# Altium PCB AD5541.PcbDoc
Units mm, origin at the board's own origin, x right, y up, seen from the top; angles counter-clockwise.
Board outline 64.13 x 29.21 mm, 2 copper layers (Top Layer, Bottom Layer); 40 components, 20 nets, 121 pads, 208 vias.
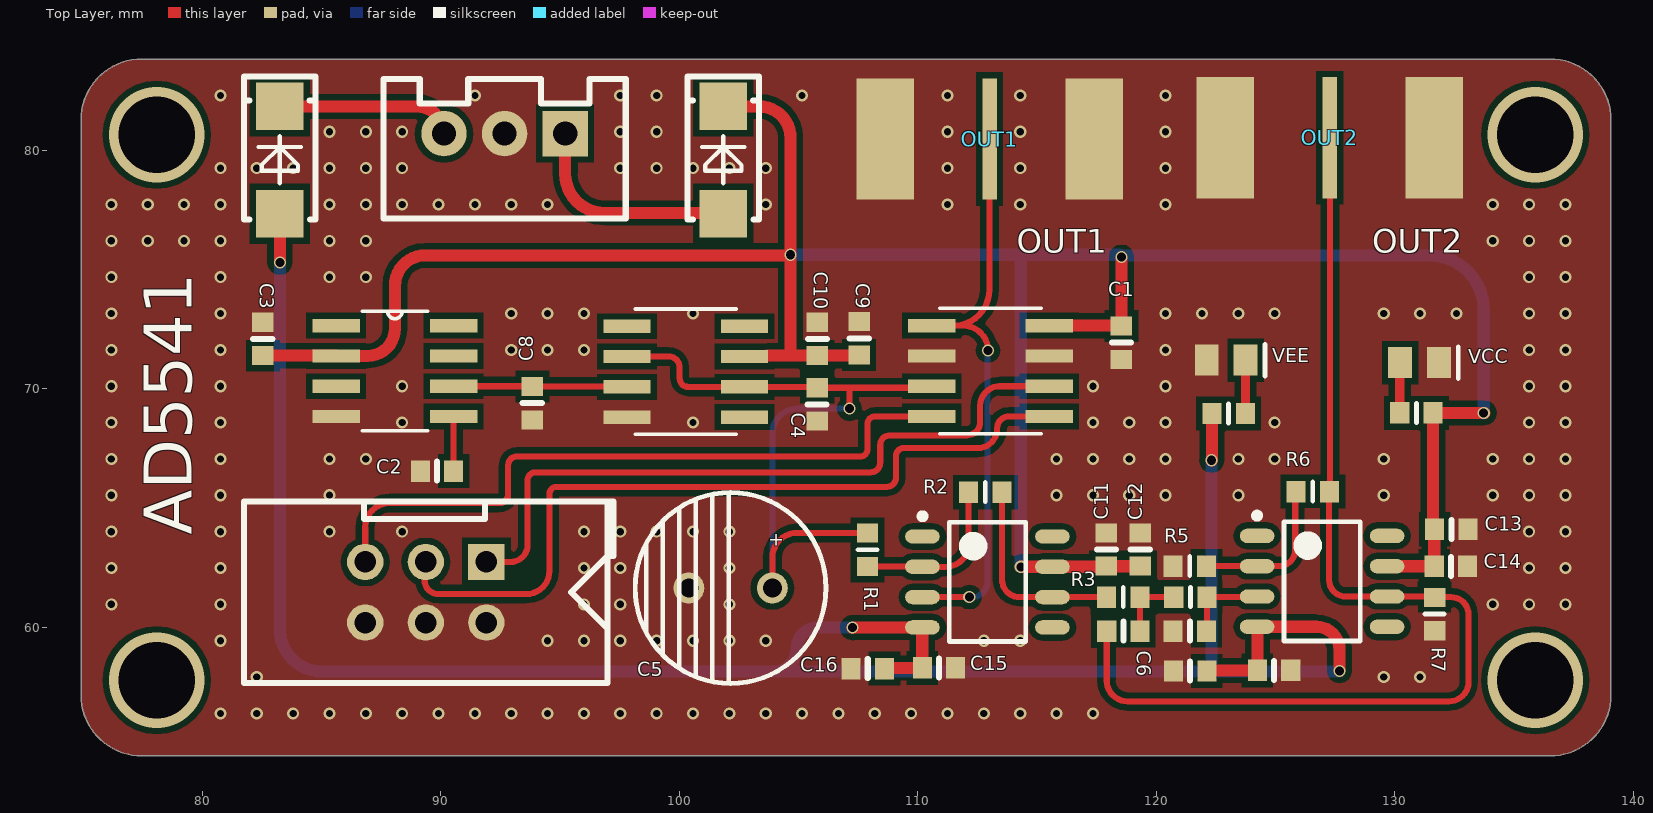
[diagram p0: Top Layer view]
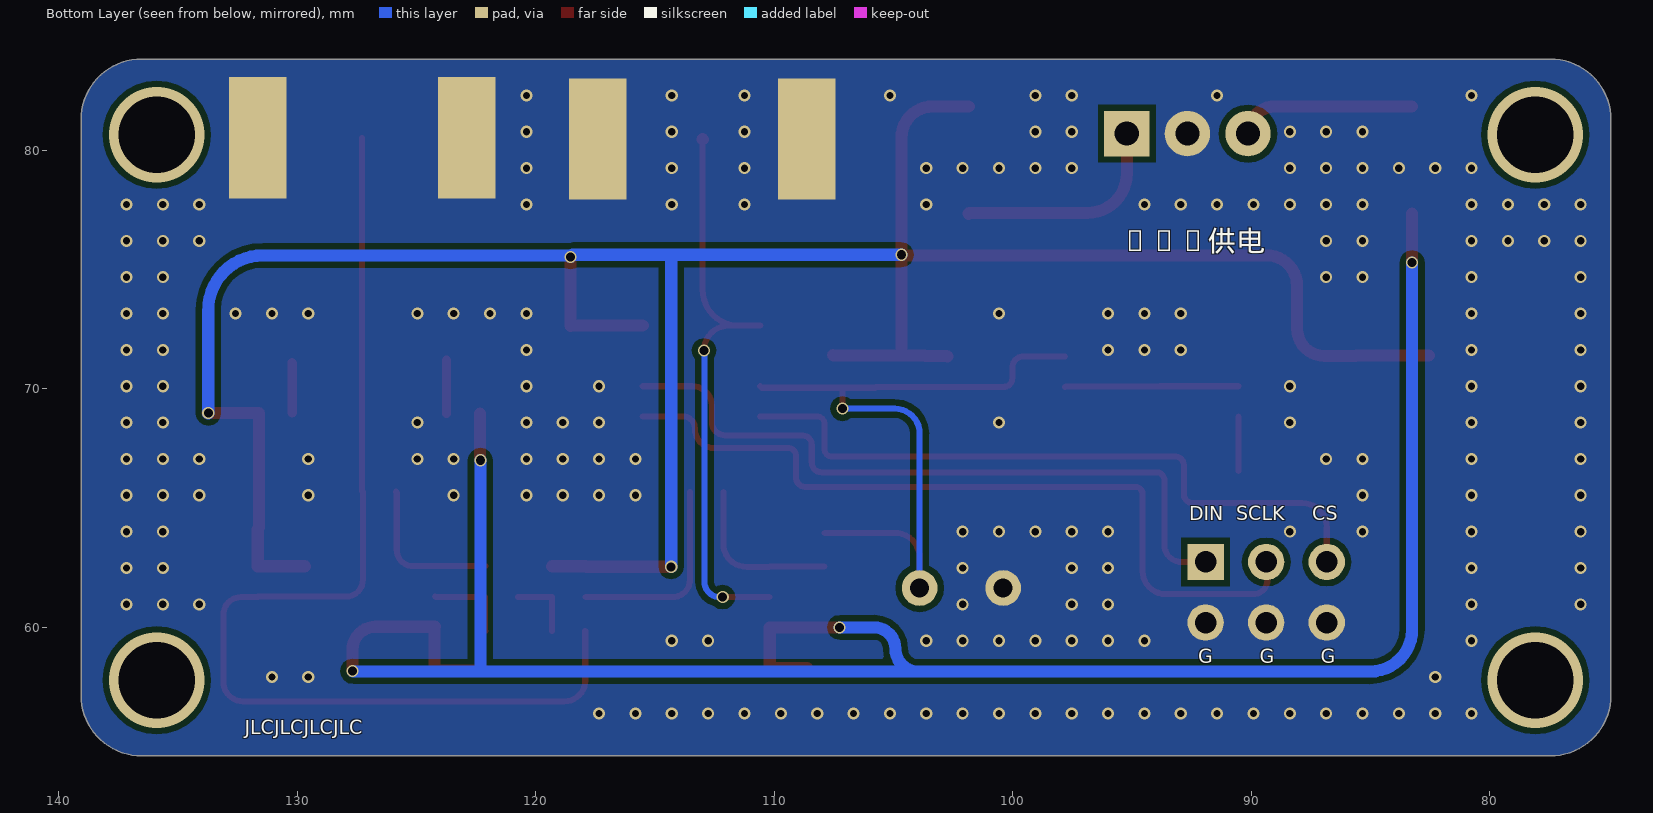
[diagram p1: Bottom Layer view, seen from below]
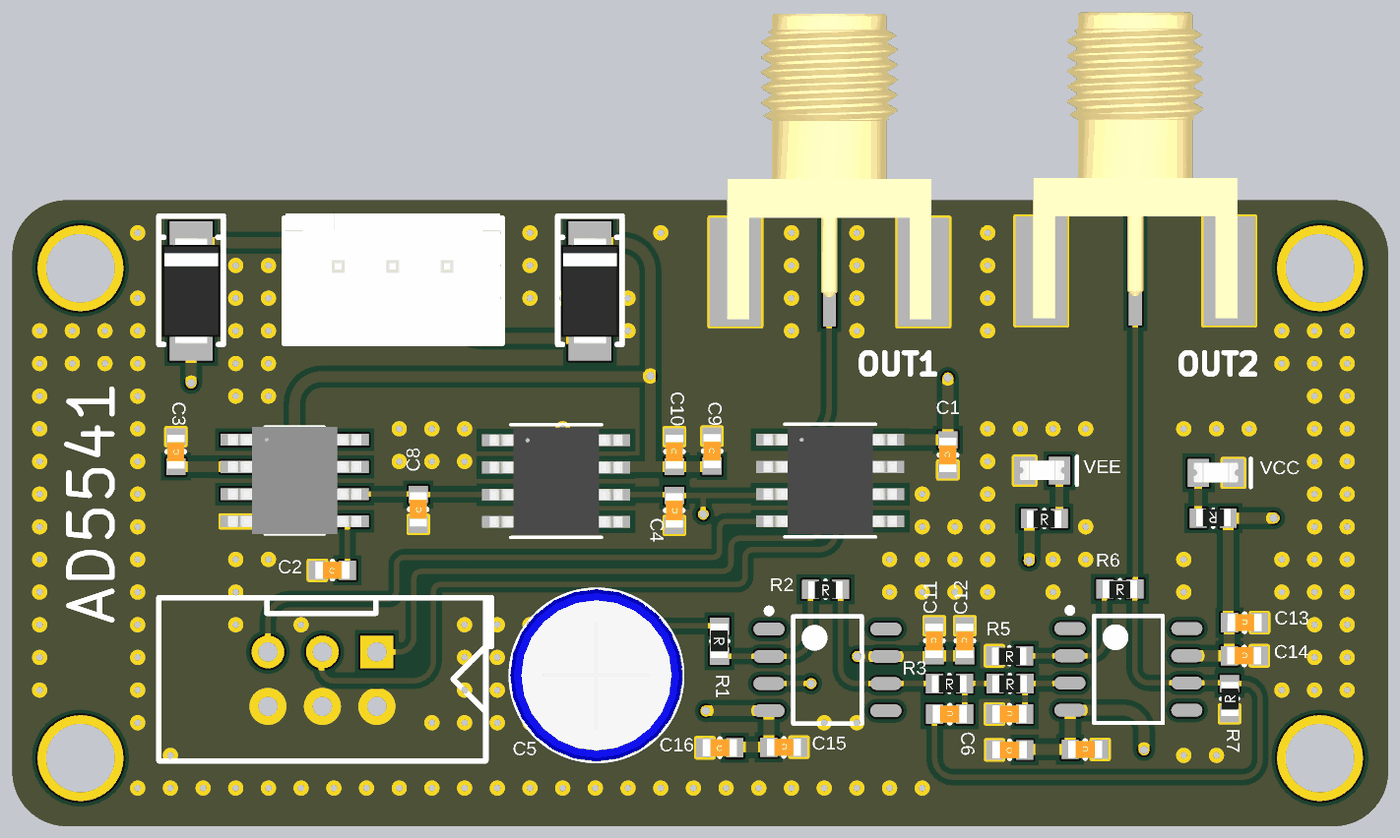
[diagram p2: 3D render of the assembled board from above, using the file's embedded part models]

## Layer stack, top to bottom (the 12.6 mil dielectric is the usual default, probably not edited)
Top Solder: solder mask 0.0102, Solder Resist, Dk 3.5
Top Layer: signal copper 0.0356
Dielectric 1: dielectric 0.32, FR-4, Dk 4.8
Bottom Layer: signal copper 0.0356
Bottom Solder: solder mask 0.0102, Solder Resist, Dk 3.5

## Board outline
74.93,57.15 ccw(c77.47,57.15) 77.47,54.61 136.525,54.61 ccw(c136.525,57.15) 139.065,57.15 139.065,81.28 ccw(c136.525,81.28) 136.525,83.82 77.47,83.82 ccw(c77.47,81.28) 74.93,81.28

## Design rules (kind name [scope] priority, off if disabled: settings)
Clearance [All] p1: gap=0.254 ignorepadtopadclearanceinfootprint=FALSE except(0: Arc-Hole Track-Hole SMDPad-Hole THPad-Hole Via-Hole Fill-Hole Poly-Hole Region-Hole Text-Hole)
PolygonConnect [All] p1: connectstyle=Direct reliefconductorwidth=0.254 reliefentries=4 polygonreliefangle="90 Angle" airgapwidth=0.254
RoutingVias [All] p1: holewidth=0.711 width=1.27 viastyle="Through Hole" minholewidth=0.711 minwidth=1.27 maxholewidth=0.711 maxwidth=1.27
SolderMaskExpansion [All] p1: expansion=0.102 istentingtop=FALSE
Width [All] p1: maxlimit=2.54 minlimit=0.254 preferedwidth=0.254
30 further rules are at their usual default settings.

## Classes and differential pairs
component class AD5541: C1 C2 C3 C4 C5 C6 C8 C9 C10 C11 C12 C13 C14 C15 C16 OUT1 OUT2 R1 R2 R3 R5 R6 R7

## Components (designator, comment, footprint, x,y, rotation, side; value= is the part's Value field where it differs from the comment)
C1 "Cap-S" C0603-L 118.542,71.933 r270 top value=100nF
C2 "Cap-S" C0603-L 89.851,66.548 r0 top value=1uF
C3 "Cap-S" C0603-L 82.55,72.085 r90 top value=1uF
C4 "Cap-S" C0603-L 105.791,69.342 r90 top value=100nF
C5 "C" C-DIP-8 102.184,61.646 r180 top value=10uF
C6 "Cap-S" C0603-L 118.629,59.842 r180 top value=4.7nF
C7 "Cap-S" C0603-L 121.412,59.842 r180 top value=4.7nF
C8 "Cap-S" C0603-L 93.853,69.393 r90 top value=10uF
C9 "Cap-S" C0603-L 107.544,72.111 r270 top value=100nF
C10 "Cap-S" C0603-L 105.791,72.085 r270 top value=10uF
C11 "Cap-S" C0603-L 117.907,63.26 r270 top value=100nF
C12 "Cap-S" C0603-L 119.329,63.26 r270 top value=10uF
C13 "Cap-S" C0603-L 132.374,64.11 r180 top value=100nF
C14 "Cap-S" C0603-L 132.359,62.56 r180 top value=10uF
C15 "Cap-S" C0603-L 110.896,58.293 r180 top value=100nF
C16 "Cap-S" C0603-L 107.91,58.268 r0 top value=10uF
C17 "Cap-S" C0603-L 124.943,58.191 r180 top value=100nF
C18 "Cap-S" C0603-L 121.423,58.166 r0 top value=10uF
D1 "D" D-SMA 101.854,79.586 r90 top
D2 "D" D-SMA 83.263,79.586 r90 top
J1 "DC-6P" DC-6P 87.224,61.341 r180 top
J2 "Power-3P" SIPA03 95.225,80.696 r180 top
LED1 "LED" Led-0805_L 131.039,71.095 r0 top
LED2 "LED" Led-0805_L 122.936,71.196 r0 top
OUT1 "SMA" SMA1 113.017,80.467 r270 top
OUT2 "SMA" SMA1 127.279,80.518 r270 top
R1 "R" R0603-L 107.899,63.246 r270 top value=28K
R2 "R" R0603-L 112.838,65.659 r0 top value=28K
R3 "R" R0603-L 118.618,61.265 r0 top value=330R
R4 "R" R0603-L 121.437,61.265 r0 top value=240R
R5 "R" R0603-L 121.412,62.56 r0 top value=1K
R6 "R" R0603-L 126.568,65.684 r0 top value=1K
R7 "R" R0603-L 131.674,60.554 r90 top value=1K
U1 "AD5541ARZ" R_8_ADI 113.055,70.739 r0 top
U2 "REF5025AID" D8 88.087,70.739 r0 top
U3 "AD8628ARZ" R_8_ADI 100.279,70.714 r0 top
U4 "OPA192" SOIC127P600X175-8N 112.928,61.9 r0 top
U5 "OPA192" SOIC127P600X175-8N 126.956,61.925 r0 top
VCC "R" R0603-L 130.912,68.986 r180 top value=1K (schematic designator R8)
VEE "R" R0603-L 123.038,68.961 r0 top value=1K (schematic designator R9)

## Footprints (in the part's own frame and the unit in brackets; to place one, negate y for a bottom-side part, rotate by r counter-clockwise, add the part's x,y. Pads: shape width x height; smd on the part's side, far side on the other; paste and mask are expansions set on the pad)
C0603-L [mm] "贴片电容0603 高密度"
  rect 0.8x0.9 smd: 1(-0.7,0) 2(0.7,0)
  silkscreen extent 0,-0.39 0,0.41, body extent -0.8,-0.4 0.8,0.41, height 0.88
C-DIP-8 [mm] "3.5*8*12mm  470uF/25V"
  round 1.3 / inner round 1.3 / far side round 1.5 hole 0.8: 1(-1.725,0) 2(1.775,0)
  silkscreen extent -3.97,-4 4.03,4, body extent -4,-4.03 4.05,4.03, height 11.83
D8 [mil]
  rect 78x22 smd: 1(-97,75) 2(-97,25) 3(-97,-25) 4(-97,-75) 5(97,-75) 6(97,-25) 7(97,25) 8(97,75)
  silkscreen extent -54,-98 54,98, body extent -122,-99 122,99, height 69
D-SMA [mm]
  rect 2x2 smd: 1(-2.25,0) 2(2.25,0)
  silkscreen extent -2.5,-1.5 3.5,1.5, body extent -2.5,-1.35 2.5,1.35, height 2.15
DC-6P [mil]
  rect 60x60 hole 35.43: 1(-185,-55)
  round 60 hole 35.43: 2(-85,-55) 3(15,-55) 4(15,45) 5(-85,45) 6(-185,45)
  silkscreen extent -395,-155 215,145, body extent -386,-156 216,145, height 236
Led-0805_L [mm] "贴片LED0805-高密度"
  rect 1x1.3 smd: 1(-0.813,0) 2(0.813,0)
  silkscreen extent 1.63,-0.66 1.63,0.66, body extent -1.03,-0.44 1.03,0.47, height 0.85
R0603-L [mm] "贴片电阻0603 高密度"
  rect 0.8x0.9 smd: 1(-0.7,0) 2(0.7,0)
  silkscreen extent 0,-0.39 0,0.41, body extent -0.81,-0.43 0.79,0.39, height 0.53
R_8_ADI [mil]
  rect 78x22 smd paste+0 mask+0: 1(-97,75) 2(-97,25) 3(-97,-25) 4(-97,-75) 5(97,-75) 6(97,-25) 7(97,25) 8(97,75)
  silkscreen extent -84,-104 84,104, body extent -122,-99 122,99, height 69
SIPA03 [mil]
  rect 75x75 hole 40: 1(0,0)
  round 75 hole 40: 2(100,0) 3(200,0)
  silkscreen extent -100,-90 300,140, body extent -96,-99 298,137, height 276
SMA1 [mil]
  rect 200x24 smd: 1(0,0)
  rect 200x95 smd: 2(0,172.5) 2(0,-172.5)
  rect 200x95 smd far side mask+4: 2(0,172.5)
  rect 200x95 smd far side: 2(0,-172.5)
  body extent -475,-187 87,187, height 171
SOIC127P600X175-8N [mm] "SOIC, 8-Leads, Body 4.91x3.90mm, Pitch 1.27mm, IPC Medium Density"
  oval 1.45x0.6 smd: 1(-2.725,1.905) 2(-2.725,0.635) 3(-2.725,-0.635) 4(-2.725,-1.905) 5(2.725,-1.905) 6(2.725,-0.635) 7(2.725,0.635) 8(2.725,1.905)
  silkscreen extent -2.85,-2.5 1.6,2.88, body extent -2,-2.5 2,2.5, height 1.75

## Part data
C1 C2 C3 C4 C6 C7 C8 C9 C10 C11 C12 C13 C14 C15 C16 C17 C18: "贴片瓷片电容"
C5: library part Cap-Pol-ER, "极性直插电解电容"
D1 D2: library part Diode, "二极管"
J2: "供电端子"
LED1 LED2: "发光二极管"
R1 R2 R3 R4 R5 R6 R7 VCC VEE: library part Res, "贴片电阻"
U1 U3: "No Description Available", Mfr_Name="Analog Devices Inc"
U2: "No Description Available", Mfr_Name="Texas Instruments"

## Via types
v1: diameter 0.508, hole 0.305, Top Layer to Bottom Layer, 193 vias
v2: diameter 0.508, hole 0.381, Top Layer to Bottom Layer, 11 vias
v3: diameter 4, hole 3.2, Top Layer to Bottom Layer, 4 vias

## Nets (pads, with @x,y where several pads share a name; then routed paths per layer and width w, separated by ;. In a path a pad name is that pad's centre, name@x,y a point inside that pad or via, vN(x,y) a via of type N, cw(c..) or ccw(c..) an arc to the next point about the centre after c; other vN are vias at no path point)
CS: J1.3 U1.4 | length 28.8
  Top Layer w0.254: J1.3 86.843,64.186 cw(c87.859,64.186) 87.859,65.202 92.456,65.202 ccw(c92.456,65.583) 92.837,65.583 92.837,66.802 cw(c93.193,66.802) 93.193,67.158 107.594,67.158 ccw(c107.594,67.462) 107.899,67.462 107.899,68.529 cw(c108.204,68.529) 108.204,68.834 U1.4
DAC_O: OUT1.1 U1.1 U4.3 | length 24.4
  Top Layer w0.254: U4.3 v2(112.166,61.265) ; U1.1 111.912,72.644 cw(c111.912,71.603) v2(112.954,71.603) ; U1.1@111.506,72.644 ccw(c111.506,74.143) 113.005,74.143 OUT1.1@113.005,80.454
  Top Layer w0.508: OUT1.1@113.005,80.454 OUT1.1
  Bottom Layer w0.254: v2(112.166,61.265) 112.293,61.265 ccw(c112.293,61.9) 112.928,61.9 112.928,71.577 cw(c112.954,71.577) v2(112.954,71.603)
DIN: J1.1 U1.6 | length 29.6
  Top Layer w0.254: J1.1 92.939,62.738 ccw(c92.939,63.449) 93.65,63.449 93.65,66.167 cw(c93.98,66.167) 93.98,66.497 108.026,66.497 ccw(c108.026,66.904) 108.433,66.904 108.433,67.64 cw(c108.839,67.64) 108.839,68.047 112.065,68.047 ccw(c112.065,68.605) 112.624,68.605 112.624,69.291 cw(c113.436,69.291) 113.436,70.104 U1.6
GND: C1.2 C2.1 C3.2 C4.1 C5.2 C7.2 C8.1 C9.1 C10.1 C11.1 C12.1 C13.1 C14.1 C15.1 C16.1 C17.1 C18.1 J1.4 J1.5 J1.6 J2.2 LED1.2 LED2.1 OUT1.2 OUT2.2 R5.1 R7.1 U1.2 U1.7 U2.4 U3.4
  other v1: 80.772,56.388 82.296,56.388 83.82,56.388 85.344,56.388 86.868,56.388 88.392,56.388 89.916,56.388 91.44,56.388 92.964,56.388 94.488,56.388 96.012,56.388 97.536,56.388 99.06,56.388 100.584,56.388 102.108,56.388 103.632,56.388 105.156,56.388 106.68,56.388 108.204,56.388 109.728,56.388 111.252,56.388 112.776,56.388 114.3,56.388 115.824,56.388 117.348,56.388 82.296,57.912 129.54,57.912 131.064,57.912 80.772,59.436 94.488,59.436 96.012,59.436 97.536,59.436 99.06,59.436 100.584,59.436 102.108,59.436 103.632,59.436 112.776,59.436 114.3,59.436 76.2,60.96 80.772,60.96 96.012,60.96 97.536,60.96 102.108,60.96 134.112,60.96 135.636,60.96 137.16,60.96 76.2,62.484 80.772,62.484 96.012,62.484 97.536,62.484 102.108,62.484 135.636,62.484 137.16,62.484 76.2,64.008 80.772,64.008 85.344,64.008 88.392,64.008 96.012,64.008 97.536,64.008 99.06,64.008 100.584,64.008 102.108,64.008 135.636,64.008 137.16,64.008 76.2,65.532 80.772,65.532 85.344,65.532 115.824,65.532 117.348,65.532 118.872,65.532 120.396,65.532 123.444,65.532 129.54,65.532 134.112,65.532 135.636,65.532 137.16,65.532 76.2,67.056 80.772,67.056 85.344,67.056 86.868,67.056 115.824,67.056 117.348,67.056 118.872,67.056 120.396,67.056 123.444,67.056 124.968,67.056 129.54,67.056 134.112,67.056 135.636,67.056 137.16,67.056 76.2,68.58 80.772,68.58 88.392,68.58 100.584,68.58 117.348,68.58 118.872,68.58 120.396,68.58 124.968,68.58 135.636,68.58 137.16,68.58 76.2,70.104 80.772,70.104 88.392,70.104 117.348,70.104 120.396,70.104 135.636,70.104 137.16,70.104 76.2,71.628 80.772,71.628 92.964,71.628 94.488,71.628 96.012,71.628 120.396,71.628 135.636,71.628 137.16,71.628 76.2,73.152 80.772,73.152 92.964,73.152 94.488,73.152 96.012,73.152 100.584,73.152 120.396,73.152 121.92,73.152 123.444,73.152 124.968,73.152 129.54,73.152 131.064,73.152 132.588,73.152 135.636,73.152 137.16,73.152 76.2,74.676 80.772,74.676 85.344,74.676 86.868,74.676 135.636,74.676 137.16,74.676 76.2,76.2 77.724,76.2 79.248,76.2 80.772,76.2 85.344,76.2 86.868,76.2 134.112,76.2 135.636,76.2 137.16,76.2 76.2,77.724 77.724,77.724 79.248,77.724 80.772,77.724 85.344,77.724 86.868,77.724 88.392,77.724 89.916,77.724 91.44,77.724 92.964,77.724 94.488,77.724 103.632,77.724 111.252,77.724 114.3,77.724 120.396,77.724 134.112,77.724 135.636,77.724 137.16,77.724 80.772,79.248 82.296,79.248 83.82,79.248 85.344,79.248 86.868,79.248 88.392,79.248 97.536,79.248 99.06,79.248 100.584,79.248 102.108,79.248 103.632,79.248 111.252,79.248 114.3,79.248 120.396,79.248 85.344,80.772 86.868,80.772 88.392,80.772 97.536,80.772 99.06,80.772 111.252,80.772 114.3,80.772 120.396,80.772 80.772,82.296 91.44,82.296 97.536,82.296 99.06,82.296 105.156,82.296 111.252,82.296 114.3,82.296 120.396,82.296
NetC2_2: C2.2 U2.5 | length 2.3
  Top Layer w0.254: C2.2 U2.5
NetC6_1: C6.1 R3.2 R4.1 | length 2.8
  Top Layer w0.254: C6.1 119.329,61.254 R3.2 R4.1
NetC6_2: C6.2 OUT2.1 R6.2 R7.2 U5.6 | length 46.3
  Top Layer w0.254: C6.2 117.929,57.763 ccw(c118.796,57.763) 118.796,56.896 132.283,56.896 ccw(c132.283,57.709) 133.096,57.709 133.096,60.528 ccw(c132.359,60.528) 132.359,61.265 131.662,61.265 cw(c131.662,61.29) 131.637,61.29 U5.6 127.94,61.29 cw(c127.94,61.976) 127.254,61.976 127.254,65.684 R6.2 127.279,65.696 OUT2.1
NetC7_1: C7.1 R4.2 U5.3 | length 3.5
  Top Layer w0.254: C7.1 ccw(c122.112,59.868) 122.137,59.868 R4.2 124.206,61.265 U5.3
NetC8_2: C8.2 U2.6 U3.3 | length 7.3
  Top Layer w0.254: U2.6 93.842,70.104 C8.2 97.801,70.093 U3.3
NetD1_1: D1.1 J2.1 | length 9.3
  Top Layer w0.508: J2.1 95.225,79.019 ccw(c96.876,79.019) 96.876,77.368 101.822,77.368 cw(c101.822,77.336) D1.1
NetD2_2: D2.2 J2.3 | length 7.5
  Top Layer w0.508: D2.2 89.004,81.836 cw(c89.004,80.696) J2.3
NetLED1_1: LED1.1 VCC.2 | length 2.1
  Top Layer w0.381: VCC.2 130.212,71.08 LED1.1
NetLED2_2: LED2.2 VEE.2 | length 2.2
  Top Layer w0.381: VEE.2 123.738,71.185 LED2.2
NetR1_2: R1.2 R2.1 U4.2 | length 7
  Top Layer w0.254: R1.2 110.192,62.546 U4.2 111.176,62.535 ccw(c111.176,63.5) 112.141,63.5 112.141,65.659 R2.1
NetR2_2: R2.2 R3.1 U4.6 | length 8.5
  Top Layer w0.254: R2.2 113.538,62.001 ccw(c114.275,62.001) 114.275,61.265 U4.6 R3.1
NetR5_2: R5.2 R6.1 U5.2 | length 6.6
  Top Layer w0.254: R5.2 U5.2 125.146,62.56 ccw(c125.146,63.246) 125.832,63.246 125.832,65.648 cw(c125.868,65.648) R6.1
REF: C4.2 C5.1 R1.1 U1.3 U3.2 U3.6 | length 30.8
  Top Layer w0.254: U3.2 99.568,71.349 cw(c99.568,70.891) 100.025,70.891 100.025,70.434 ccw(c100.381,70.434) 100.381,70.079 U3.6 105.754,70.079 C4.2 107.086,70.042 ; C5.1 103.909,62.913 cw(c104.953,62.913) 104.953,63.957 107.899,63.957 R1.1 ; v2(107.137,69.164) 107.137,69.991 ccw(c107.086,69.991) 107.086,70.042 ; U1.3 110.53,70.042 107.086,70.042
  Bottom Layer w0.254: C5.1 103.909,68.12 cw(c104.953,68.12) 104.953,69.164 v2(107.137,69.164)
SCLK: J1.2 U1.5 | length 33.3
  Top Layer w0.254: J1.2 ccw(c89.383,62.687) 89.332,62.687 89.332,61.976 ccw(c89.916,61.976) 89.916,61.392 93.599,61.392 ccw(c93.599,62.357) 94.564,62.357 94.564,65.583 cw(c94.869,65.583) 94.869,65.888 108.712,65.888 ccw(c108.712,66.269) 109.093,66.269 109.093,67.183 cw(c109.423,67.183) 109.423,67.513 112.522,67.513 ccw(c112.522,68.326) 113.335,68.326 113.335,68.351 cw(c113.817,68.351) 113.817,68.834 U1.5
VCC: C1.1 C3.1 C9.2 C10.2 C11.2 C12.2 C13.2 C14.2 D1.2 U1.8 U2.2 U3.7 U4.7 U5.7 VCC.1 | length 112.3
  Top Layer w0.508: C3.1 85.612,71.385 U2.2 86.944,71.374 ccw(c86.944,72.517) 88.087,72.517 88.087,74.32 cw(c89.357,74.32) 89.357,75.59 104.648,75.59 v2(104.673,75.616) ; D1.2 103.355,81.836 cw(c103.355,80.518) 104.673,80.518 v2(104.673,75.616) ; U3.7 102.768,71.374 103.679,71.374 103.69,71.385 104.813,71.385 ; C9.2 107.518,71.385 C10.2 104.813,71.385 ; v2(114.325,62.535) U4.7 117.881,62.535 C11.2 C12.2 ; U1.8 118.531,72.644 C1.1 v2(118.542,75.527) ; U5.7 C14.2 131.659,64.095 C13.2 131.612,64.172 VCC.1 v2@133.758,68.986 ; v2(104.673,75.616) 104.673,71.525 ccw(c104.813,71.525) 104.813,71.385
  Bottom Layer w0.508: v2(104.673,75.616) 114.3,75.616 ; v2(114.325,62.535) 114.325,75.59 ccw(c114.3,75.59) 114.3,75.616 ; v2@133.731,68.961 133.731,73.304 ccw(c131.445,73.304) 131.445,75.59 118.605,75.59 v2(118.542,75.527) ccw(c118.453,75.527) 118.453,75.616 114.3,75.616
  other v2: 133.731,68.986
VEE: C15.2 C16.2 C17.2 C18.2 D2.1 U4.4 U5.4 VEE.1 | length 93.1
  Top Layer w0.508: v2(83.263,75.287) D2.1 ; v2@107.264,59.969 cw(c107.29,59.969) 107.29,59.995 U4.4 110.196,59.988 C15.2 108.636,58.293 C16.2 ; C18.2 122.149,58.191 C17.2 124.243,60.009 U5.4 126.721,60.02 cw(c126.721,59.055) 127.686,59.055 v2(127.686,58.166) ; v2(122.326,67.001) 122.338,67.001 VEE.1
  Bottom Layer w0.508: v2(83.263,75.287) 83.263,59.917 ccw(c85.039,59.917) 85.039,58.141 103.962,58.141 ; v2(107.264,59.995) 105.816,59.995 ccw(c105.816,59.106) 104.927,59.106 cw(c103.962,59.106) 103.962,58.141 ; v2(122.326,67.001) 122.326,58.141 ; v2@127.66,58.141 122.326,58.141 ; 103.962,58.141 122.326,58.141
pads on no net: U2.1 U2.3 U2.7 U2.8 U3.1 U3.5 U3.8 U4.1 U4.5 U4.8 U5.1 U5.5 U5.8
copper on no net:
  other v3: 78.105,57.785 135.89,57.785 78.105,80.645 135.89,80.645

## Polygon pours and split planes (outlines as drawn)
GND on Top Layer "GND_TOP" (solid, pour order 0): 74.93,57.15 ccw(c77.47,57.15) 77.47,54.61 136.525,54.61 ccw(c136.525,57.15) 139.065,57.15 139.065,81.28 ccw(c136.525,81.28) 136.525,83.82 77.47,83.82 ccw(c77.47,81.28) 74.93,81.28
GND on Bottom Layer "GND_BUT" (solid, pour order 1): 74.93,57.15 ccw(c77.47,57.15) 77.47,54.61 136.525,54.61 ccw(c136.525,57.15) 139.065,57.15 139.065,81.28 ccw(c136.525,81.28) 136.525,83.82 77.47,83.82 ccw(c77.47,81.28) 74.93,81.28

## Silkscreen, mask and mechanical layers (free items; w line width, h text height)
Top Overlay:
  text "OUT1" at 114.148,75.692 h1
  text "OUT2" at 129.057,75.692 h1
  text "AD5541" at 79.578,63.881 h2 r90
Bottom Overlay:
  text "±5V供电" at 95.479,75.48 h1.52
  text "DIN" at 92.608,64.284 h1
  text "CS" at 87.452,64.273 h1
  text "SCLK" at 90.627,64.273 h1
  text "G" at 87.097,58.279 h1
  text "G" at 89.662,58.279 h1
  text "G" at 92.227,58.279 h1
  text "JLCJLCJLCJLC" at 132.209,55.307 h1
Bottom Solder:
  rectangle: 130.175,77.902 132.588,83.033
  rectangle: 116.053,77.699 118.466,82.829
Mechanical 1:
  the board outline again, w0.254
